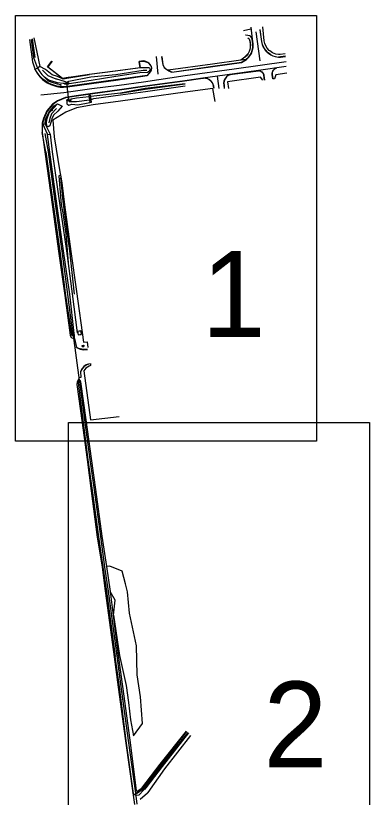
# Model space of a CAD drawing. Extents: x -866693 to -866303, y -1041966 to -1040244.
# Drawn here: x -866546.05 to -866533.7, y -1040634.99 to -1040607.7 of the extents above; entities that cross this region are included whole.
import ezdxf

# ---------------------------------------------------------------- set-up
doc = ezdxf.new("R2010")
doc.units = 0
doc.layers.add('Formát', color=7, linetype='Continuous')
doc.layers.add('Legenda', color=7, linetype='Continuous')

msp = doc.modelspace()

# ---------------------------------------------------------------- linework, layer by layer
at = {"layer": 'Legenda'}
for p, q in [((-866537.835, -1040608.174), (-866538.095, -1040608.233)), ((-866537.786, -1040608.522), (-866537.834, -1040608.107)), ((-866537.668, -1040608.26), (-866537.526, -1040609.272)), ((-866545.569, -1040608.535), (-866545.459, -1040609.311)), ((-866545.515, -1040608.528), (-866545.427, -1040609.164)), ((-866545.366, -1040609.158), (-866545.468, -1040608.506)), ((-866545.412, -1040608.473), (-866545.203, -1040609.471)), ((-866545.427, -1040609.164), (-866545.293, -1040609.528)), ((-866541.144, -1040609.123), (-866541.089, -1040609.746)), ((-866538.005, -1040609.227), (-866538.188, -1040609.253)), ((-866541.706, -1040609.521), (-866541.738, -1040609.297)), ((-866541.698, -1040609.526), (-866541.731, -1040609.302)), ((-866541.377, -1040609.52), (-866541.698, -1040609.526)), ((-866538.944, -1040610.248), (-866539.007, -1040609.813)), ((-866538.476, -1040609.752), (-866538.478, -1040609.748)), ((-866537.577, -1040609.634), (-866538.476, -1040609.752)), ((-866544.265, -1040610.05), (-866544.267, -1040610.025)), ((-866544.189, -1040610.664), (-866544.265, -1040610.048)), ((-866541.53, -1040610.27), (-866540.13, -1040610.079)), ((-866544.471, -1040610.108), (-866544.483, -1040610.179)), ((-866542.394, -1040610.407), (-866541.53, -1040610.27)), ((-866543.93, -1040610.582), (-866544.119, -1040610.621)), ((-866544.265, -1040610.667), (-866544.206, -1040610.666)), ((-866544.187, -1040610.697), (-866544.185, -1040610.664)), ((-866544.757, -1040611.028), (-866544.781, -1040610.991)), ((-866545.118, -1040611.463), (-866544.94, -1040611.848)), ((-866545.021, -1040611.488), (-866544.848, -1040611.839)), ((-866545.001, -1040612.458), (-866545.121, -1040611.78)), ((-866544.249, -1040615.9), (-866544.222, -1040616.326)), ((-866543.892, -1040618.711), (-866543.781, -1040618.695)), ((-866543.892, -1040618.711), (-866543.874, -1040618.84)), ((-866543.89, -1040618.712), (-866543.782, -1040618.696)), ((-866543.89, -1040618.712), (-866543.873, -1040618.839)), ((-866543.874, -1040618.84), (-866543.763, -1040618.824)), ((-866543.873, -1040618.839), (-866543.765, -1040618.823)), ((-866543.782, -1040618.696), (-866543.765, -1040618.823)), ((-866543.781, -1040618.695), (-866543.763, -1040618.824)), ((-866544.047, -1040618.859), (-866543.832, -1040620.423)), ((-866543.736, -1040619.209), (-866543.676, -1040619.202)), ((-866543.736, -1040619.209), (-866543.732, -1040619.253)), ((-866543.734, -1040619.211), (-866543.677, -1040619.203)), ((-866543.734, -1040619.211), (-866543.731, -1040619.251)), ((-866543.732, -1040619.253), (-866543.672, -1040619.246)), ((-866543.731, -1040619.251), (-866543.674, -1040619.244)), ((-866543.677, -1040619.203), (-866543.674, -1040619.244)), ((-866543.676, -1040619.202), (-866543.672, -1040619.246)), ((-866543.584, -1040619.898), (-866543.668, -1040619.959)), ((-866543.469, -1040619.855), (-866543.584, -1040619.898)), ((-866543.469, -1040619.855), (-866543.472, -1040619.853)), ((-866543.784, -1040620.12), (-866543.789, -1040620.117)), ((-866543.727, -1040620.025), (-866543.784, -1040620.12)), ((-866543.668, -1040619.959), (-866543.727, -1040620.025)), ((-866543.858, -1040620.4), (-866543.864, -1040620.504)), ((-866543.832, -1040620.423), (-866543.826, -1040620.485)), ((-866543.864, -1040620.504), (-866543.706, -1040621.824)), ((-866543.826, -1040620.485), (-866543.648, -1040621.813)), ((-866543.783, -1040620.484), (-866543.603, -1040621.806)), ((-866543.706, -1040621.824), (-866543.531, -1040623.204)), ((-866543.648, -1040621.813), (-866543.462, -1040623.195)), ((-866543.603, -1040621.806), (-866543.42, -1040623.162)), ((-866543.462, -1040623.195), (-866543.314, -1040624.254)), ((-866543.42, -1040623.162), (-866543.268, -1040624.239)), ((-866543.531, -1040623.204), (-866543.385, -1040624.271)), ((-866543.385, -1040624.271), (-866543.156, -1040625.894)), ((-866543.314, -1040624.254), (-866543.089, -1040625.88)), ((-866543.268, -1040624.239), (-866543.037, -1040625.869)), ((-866543.156, -1040625.894), (-866543.005, -1040626.955)), ((-866543.089, -1040625.88), (-866542.944, -1040626.947)), ((-866543.037, -1040625.869), (-866542.884, -1040626.927)), ((-866543.005, -1040626.955), (-866542.884, -1040627.79)), ((-866542.944, -1040626.947), (-866542.825, -1040627.793)), ((-866542.759, -1040626.92), (-866542.884, -1040626.927)), ((-866542.884, -1040626.927), (-866542.755, -1040627.8)), ((-866542.333, -1040627.087), (-866542.759, -1040626.92)), ((-866542.215, -1040627.528), (-866542.333, -1040627.087)), ((-866542.149, -1040627.815), (-866542.215, -1040627.528)), ((-866542.884, -1040627.79), (-866542.576, -1040630.066)), ((-866542.825, -1040627.793), (-866542.518, -1040630.045)), ((-866542.755, -1040627.8), (-866542.47, -1040630.035)), ((-866542.581, -1040628.107), (-866542.755, -1040627.8)), ((-866542.081, -1040628.559), (-866542.149, -1040627.815)), ((-866542.641, -1040628.621), (-866542.581, -1040628.107)), ((-866542.641, -1040628.621), (-866542.43, -1040630.028)), ((-866541.837, -1040629.696), (-866542.081, -1040628.559)), ((-866541.812, -1040630.703), (-866541.837, -1040629.696)), ((-866542.425, -1040631.13), (-866542.576, -1040630.066)), ((-866542.518, -1040630.045), (-866542.376, -1040631.115)), ((-866542.47, -1040630.035), (-866542.323, -1040631.111)), ((-866542.43, -1040630.028), (-866542.191, -1040631.08)), ((-866541.691, -1040631.478), (-866541.812, -1040630.703)), ((-866542.323, -1040631.111), (-866542.068, -1040632.992)), ((-866542.191, -1040631.08), (-866542.106, -1040631.678)), ((-866542.198, -1040633.008), (-866542.425, -1040631.13)), ((-866542.376, -1040631.115), (-866542.123, -1040632.999)), ((-866541.627, -1040632.407), (-866541.691, -1040631.478)), ((-866542.106, -1040631.678), (-866542.037, -1040632.276)), ((-866542.037, -1040632.276), (-866541.942, -1040632.835)), ((-866541.942, -1040632.835), (-866541.627, -1040632.407)), ((-866541.004, -1040633.829), (-866540.091, -1040632.678)), ((-866540.995, -1040633.853), (-866540.073, -1040632.691)), ((-866540.038, -1040632.717), (-866540.97, -1040633.872)), ((-866540.022, -1040632.735), (-866540.933, -1040633.904)), ((-866541.933, -1040634.854), (-866542.198, -1040633.008)), ((-866542.123, -1040632.999), (-866541.87, -1040634.838)), ((-866542.068, -1040632.992), (-866541.843, -1040634.746)), ((-866540.838, -1040633.988), (-866539.932, -1040632.831)), ((-866541.644, -1040634.667), (-866541.004, -1040633.829)), ((-866541.626, -1040634.68), (-866540.995, -1040633.853)), ((-866540.97, -1040633.872), (-866541.601, -1040634.698)), ((-866540.933, -1040633.904), (-866541.506, -1040634.655)), ((-866541.428, -1040634.819), (-866540.838, -1040633.988)), ((-866541.506, -1040634.655), (-866541.539, -1040634.695)), ((-866541.922, -1040634.902), (-866541.965, -1040634.83)), ((-866541.921, -1040634.869), (-866541.933, -1040634.854)), ((-866541.829, -1040634.919), (-866541.922, -1040634.902)), ((-866541.89, -1040634.882), (-866541.921, -1040634.869)), ((-866541.851, -1040634.875), (-866541.89, -1040634.882)), ((-866541.87, -1040634.838), (-866541.808, -1040634.814)), ((-866541.87, -1040634.838), (-866541.826, -1040635.224)), ((-866541.817, -1040634.847), (-866541.851, -1040634.875)), ((-866541.843, -1040634.746), (-866541.825, -1040634.77)), ((-866541.755, -1040634.914), (-866541.829, -1040634.919)), ((-866541.825, -1040634.77), (-866541.808, -1040634.774)), ((-866541.794, -1040634.84), (-866541.817, -1040634.847)), ((-866541.808, -1040634.774), (-866541.644, -1040634.667)), ((-866541.808, -1040634.814), (-866541.626, -1040634.68)), ((-866541.601, -1040634.698), (-866541.794, -1040634.84)), ((-866541.572, -1040634.719), (-866541.755, -1040634.914)), ((-866541.704, -1040635.051), (-866541.451, -1040634.832)), ((-866541.539, -1040634.695), (-866541.572, -1040634.719)), ((-866541.451, -1040634.832), (-866541.428, -1040634.819))]:
    msp.add_line(p, q, dxfattribs=at)
for points in [[(-866546.052, -1040607.7), (-866535.552, -1040607.7), (-866535.552, -1040622.55), (-866546.052, -1040622.55)], [(-866544.187, -1040610.076), (-866544.189, -1040610.076), (-866544.193, -1040610.046), (-866544.19, -1040610.046)], [(-866544.267, -1040610.639), (-866544.263, -1040610.665), (-866544.265, -1040610.667)], [(-866543.492, -1040610.491), (-866543.457, -1040610.727), (-866543.407, -1040610.716), (-866543.436, -1040610.479)], [(-866544.59, -1040610.777), (-866544.426, -1040610.862), (-866544.578, -1040611.031), (-866544.729, -1040611.173), (-866544.791, -1040611.303), (-866544.8, -1040611.346), (-866544.855, -1040611.541), (-866544.911, -1040611.582), (-866544.953, -1040611.568), (-866544.974, -1040611.461), (-866544.958, -1040611.323), (-866544.878, -1040611.094)], [(-866544.202, -1040621.896), (-866533.702, -1040621.896), (-866533.702, -1040636.746), (-866544.202, -1040636.746)]]:
    msp.add_lwpolyline(points, close=True, dxfattribs=at)
for points in [[(-866537.144, -1040609.069), (-866537.142, -1040609.064), (-866537.24, -1040608.996), (-866537.265, -1040608.975), (-866537.337, -1040608.894), (-866537.402, -1040608.792), (-866537.434, -1040608.705), (-866537.461, -1040608.604), (-866537.519, -1040608.187)], [(-866536.639, -1040609.035), (-866536.821, -1040609.056), (-866536.874, -1040609.058), (-866536.972, -1040609.04), (-866537.03, -1040609.025), (-866537.087, -1040608.996), (-866537.178, -1040608.932), (-866537.205, -1040608.913), (-866537.274, -1040608.833), (-866537.319, -1040608.759), (-866537.356, -1040608.673), (-866537.379, -1040608.581), (-866537.42, -1040608.096)], [(-866540.96, -1040609.132), (-866540.917, -1040609.418), (-866540.868, -1040609.505), (-866540.813, -1040609.559), (-866540.706, -1040609.627), (-866540.639, -1040609.665), (-866540.603, -1040609.676), (-866539.17, -1040609.475), (-866538.163, -1040609.333), (-866537.995, -1040609.228), (-866537.919, -1040609.16), (-866537.843, -1040609.061), (-866537.809, -1040608.996), (-866537.78, -1040608.89), (-866537.763, -1040608.81), (-866537.762, -1040608.686), (-866537.786, -1040608.522), (-866537.817, -1040608.459), (-866537.852, -1040608.418), (-866537.876, -1040608.4), (-866538.027, -1040608.376)], [(-866537.77, -1040608.81), (-866537.767, -1040608.688), (-866537.79, -1040608.523), (-866537.816, -1040608.465), (-866537.855, -1040608.42), (-866537.877, -1040608.402), (-866538.02, -1040608.38)], [(-866537.523, -1040608.196), (-866537.467, -1040608.606), (-866537.442, -1040608.709), (-866537.409, -1040608.795), (-866537.343, -1040608.899), (-866537.269, -1040608.979), (-866537.245, -1040609.001), (-866537.144, -1040609.069), (-866537.069, -1040609.102), (-866536.991, -1040609.132), (-866536.878, -1040609.151), (-866536.802, -1040609.146), (-866536.628, -1040609.125)], [(-866537.945, -1040608.477), (-866537.899, -1040608.506), (-866537.873, -1040608.586), (-866537.86, -1040608.707), (-866537.864, -1040608.818), (-866537.874, -1040608.878), (-866537.9, -1040608.955), (-866537.936, -1040609.017), (-866538.001, -1040609.097), (-866538.052, -1040609.149), (-866538.19, -1040609.25), (-866539.18, -1040609.39), (-866540.727, -1040609.607)], [(-866537.856, -1040608.706), (-866537.859, -1040608.818), (-866537.873, -1040608.878), (-866537.898, -1040608.957), (-866537.932, -1040609.019), (-866537.994, -1040609.1), (-866538.052, -1040609.152), (-866538.188, -1040609.253), (-866539.179, -1040609.393), (-866540.724, -1040609.609)], [(-866537.945, -1040608.475), (-866537.898, -1040608.505), (-866537.872, -1040608.584), (-866537.856, -1040608.706)], [(-866538.005, -1040609.227), (-866537.999, -1040609.223), (-866537.924, -1040609.155), (-866537.851, -1040609.057), (-866537.815, -1040608.995), (-866537.77, -1040608.81)], [(-866545.459, -1040609.311), (-866545.378, -1040609.557), (-866545.314, -1040609.691), (-866545.206, -1040609.835), (-866545.11, -1040609.928), (-866544.951, -1040610.044), (-866544.825, -1040610.104), (-866544.619, -1040610.173), (-866544.494, -1040610.193), (-866544.384, -1040610.194), (-866544.159, -1040610.174), (-866543.401, -1040610.07), (-866542.548, -1040609.952), (-866541.461, -1040609.793), (-866541.346, -1040609.666), (-866541.311, -1040609.599), (-866541.302, -1040609.522), (-866541.315, -1040609.47), (-866541.344, -1040609.422), (-866541.393, -1040609.366), (-866541.434, -1040609.334), (-866541.502, -1040609.3), (-866541.579, -1040609.276), (-866541.738, -1040609.297)], [(-866540.953, -1040609.131), (-866540.913, -1040609.417), (-866540.862, -1040609.503), (-866540.809, -1040609.555), (-866540.727, -1040609.607), (-866540.724, -1040609.609), (-866540.701, -1040609.622), (-866540.699, -1040609.619), (-866540.656, -1040609.641), (-866540.601, -1040609.664), (-866540.603, -1040609.669), (-866539.171, -1040609.469), (-866538.164, -1040609.323), (-866538.005, -1040609.227)], [(-866536.628, -1040609.117), (-866536.803, -1040609.141), (-866536.878, -1040609.144), (-866536.878, -1040609.151)], [(-866545.378, -1040609.557), (-866545.293, -1040609.528), (-866545.208, -1040609.662), (-866545.134, -1040609.76), (-866545.044, -1040609.849), (-866544.913, -1040609.972), (-866544.789, -1040610.023), (-866544.602, -1040610.081), (-866544.471, -1040610.108)], [(-866543.477, -1040609.762), (-866544.194, -1040609.887), (-866544.392, -1040609.915), (-866544.592, -1040609.822), (-866544.771, -1040609.768), (-866545.013, -1040609.577), (-866545.203, -1040609.471), (-866545.293, -1040609.528)], [(-866545.177, -1040610.465), (-866544.373, -1040610.386), (-866543.389, -1040610.249), (-866542.434, -1040610.132), (-866541.584, -1040610.005), (-866540.138, -1040609.794), (-866538.42, -1040609.551), (-866536.612, -1040609.303)], [(-866536.604, -1040609.481), (-866537.578, -1040609.615), (-866538.495, -1040609.742), (-866539.516, -1040609.884), (-866540.146, -1040609.972), (-866541.546, -1040610.166), (-866542.425, -1040610.288), (-866543.364, -1040610.419), (-866543.936, -1040610.495), (-866544.314, -1040610.554), (-866544.596, -1040610.669), (-866544.761, -1040610.788), (-866544.962, -1040611.022), (-866545.084, -1040611.291), (-866545.13, -1040611.458), (-866545.121, -1040611.78), (-866545.032, -1040612.453), (-866544.765, -1040614.369), (-866544.556, -1040615.923), (-866544.339, -1040617.471), (-866544.145, -1040618.855), (-866544.109, -1040618.933), (-866544.06, -1040618.96), (-866543.995, -1040618.974), (-866543.928, -1040619.282), (-866543.848, -1040619.324), (-866543.802, -1040619.339), (-866543.688, -1040619.36), (-866543.54, -1040619.35)], [(-866541.698, -1040609.526), (-866542.571, -1040609.642), (-866543.472, -1040609.757), (-866544.195, -1040609.859), (-866544.414, -1040609.89), (-866544.94, -1040609.485), (-866544.787, -1040609.291)], [(-866544.775, -1040609.289), (-866544.929, -1040609.488), (-866544.412, -1040609.881), (-866544.216, -1040609.853), (-866543.625, -1040609.772)], [(-866541.377, -1040609.52), (-866541.35, -1040609.568), (-866541.385, -1040609.651), (-866541.446, -1040609.683), (-866541.714, -1040609.7), (-866542.553, -1040609.827), (-866543.418, -1040609.962), (-866544.187, -1040610.076)], [(-866541.706, -1040609.521), (-866542.578, -1040609.637), (-866543.48, -1040609.751), (-866543.625, -1040609.772)], [(-866541.731, -1040609.302), (-866541.574, -1040609.286), (-866541.505, -1040609.308), (-866541.437, -1040609.341), (-866541.397, -1040609.372), (-866541.35, -1040609.426), (-866541.322, -1040609.472), (-866541.31, -1040609.521), (-866541.319, -1040609.597), (-866541.354, -1040609.665), (-866541.465, -1040609.79), (-866542.56, -1040609.946)], [(-866536.952, -1040609.544), (-866536.97, -1040609.547), (-866536.995, -1040609.555), (-866537.015, -1040609.567), (-866537.037, -1040609.582), (-866537.055, -1040609.6), (-866537.074, -1040609.62), (-866537.084, -1040609.64), (-866537.101, -1040609.679), (-866537.104, -1040609.703), (-866537.103, -1040609.761), (-866537.082, -1040609.909)], [(-866536.952, -1040609.544), (-866536.951, -1040609.549), (-866536.992, -1040609.562), (-866537.011, -1040609.574), (-866537.033, -1040609.589), (-866537.068, -1040609.624), (-866537.093, -1040609.681), (-866537.097, -1040609.703), (-866537.096, -1040609.76), (-866537.074, -1040609.905)], [(-866542.56, -1040609.946), (-866543.405, -1040610.056), (-866544.16, -1040610.163), (-866544.384, -1040610.18), (-866544.492, -1040610.178), (-866544.615, -1040610.158), (-866544.819, -1040610.092), (-866544.942, -1040610.031), (-866545.102, -1040609.914), (-866545.197, -1040609.824), (-866545.302, -1040609.681), (-866545.378, -1040609.557)], [(-866545.109, -1040609.608), (-866544.924, -1040609.785), (-866544.648, -1040609.907), (-866544.622, -1040609.906), (-866544.362, -1040609.986), (-866544.267, -1040610.025), (-866544.193, -1040609.988), (-866543.423, -1040609.838), (-866542.559, -1040609.753), (-866541.595, -1040609.604), (-866541.475, -1040609.604)], [(-866538.495, -1040609.742), (-866538.568, -1040609.758), (-866538.632, -1040609.787), (-866538.696, -1040609.837), (-866538.744, -1040609.901), (-866538.779, -1040609.985), (-866538.792, -1040610.061), (-866538.789, -1040610.126), (-866538.776, -1040610.24)], [(-866538.478, -1040609.748), (-866538.495, -1040609.749), (-866538.565, -1040609.764), (-866538.63, -1040609.793), (-866538.69, -1040609.839), (-866538.74, -1040609.907), (-866538.77, -1040609.986), (-866538.781, -1040610.062), (-866538.777, -1040610.128), (-866538.768, -1040610.239)], [(-866537.355, -1040609.947), (-866537.378, -1040609.787), (-866537.38, -1040609.777), (-866537.39, -1040609.741), (-866537.397, -1040609.724), (-866537.408, -1040609.706), (-866537.435, -1040609.675), (-866537.464, -1040609.656), (-866537.488, -1040609.645), (-866537.524, -1040609.634), (-866537.578, -1040609.615)], [(-866537.577, -1040609.634), (-866537.577, -1040609.634), (-866537.577, -1040609.627), (-866537.578, -1040609.615)], [(-866537.359, -1040609.947), (-866537.386, -1040609.777), (-866537.402, -1040609.731), (-866537.442, -1040609.681), (-866537.49, -1040609.653), (-866537.527, -1040609.641), (-866537.577, -1040609.627)], [(-866536.582, -1040609.706), (-866536.967, -1040609.763), (-866537.019, -1040609.902), (-866537.068, -1040609.908)], [(-866539.134, -1040610.235), (-866539.145, -1040610.16), (-866539.159, -1040610.104), (-866539.184, -1040610.048), (-866539.229, -1040609.992), (-866539.279, -1040609.95), (-866539.324, -1040609.923), (-866539.366, -1040609.905), (-866539.41, -1040609.892), (-866539.451, -1040609.885), (-866539.496, -1040609.889), (-866539.515, -1040609.89), (-866539.517, -1040609.896), (-866540.158, -1040609.986), (-866541.544, -1040610.179), (-866542.423, -1040610.303), (-866543.357, -1040610.432), (-866543.931, -1040610.509), (-866544.31, -1040610.567), (-866544.59, -1040610.683), (-866544.63, -1040610.707), (-866544.752, -1040610.801), (-866544.949, -1040611.03), (-866545.066, -1040611.301), (-866545.118, -1040611.463), (-866545.13, -1040611.458)], [(-866544.341, -1040610.063), (-866544.393, -1040610.073), (-866544.589, -1040610.046), (-866544.773, -1040609.985), (-866544.902, -1040609.952), (-866545.044, -1040609.849)], [(-866544.193, -1040610.046), (-866544.341, -1040610.063), (-866544.336, -1040610.091), (-866544.189, -1040610.076)], [(-866544.341, -1040610.063), (-866544.283, -1040610.052), (-866544.265, -1040610.05), (-866544.251, -1040610.049), (-866544.19, -1040610.046)], [(-866540.13, -1040610.079), (-866541.533, -1040610.238), (-866542.394, -1040610.407), (-866543.325, -1040610.516), (-866543.43, -1040610.525)], [(-866539.126, -1040610.234), (-866539.136, -1040610.158), (-866539.15, -1040610.101), (-866539.181, -1040610.045), (-866539.223, -1040609.988), (-866539.275, -1040609.945), (-866539.32, -1040609.919), (-866539.362, -1040609.899), (-866539.408, -1040609.885), (-866539.451, -1040609.879), (-866539.516, -1040609.884)], [(-866537.421, -1040609.956), (-866537.507, -1040609.842), (-866538.652, -1040610.005), (-866538.625, -1040610.239)], [(-866539.088, -1040610.697), (-866539.166, -1040610.245), (-866540.133, -1040610.374), (-866541.476, -1040610.563), (-866542.391, -1040610.689), (-866543.343, -1040610.817), (-866543.926, -1040610.913), (-866544.299, -1040611.065), (-866544.752, -1040611.351), (-866544.711, -1040611.926), (-866544.511, -1040613.149), (-866544.481, -1040613.272), (-866544.442, -1040613.541), (-866544.346, -1040614.299), (-866544.121, -1040615.938), (-866543.926, -1040617.326), (-866543.679, -1040619.097), (-866543.552, -1040619.081), (-866543.529, -1040619.284)], [(-866543.317, -1040610.589), (-866542.395, -1040610.46), (-866541.515, -1040610.344), (-866540.137, -1040610.146)], [(-866544.26, -1040610.665), (-866544.116, -1040610.648), (-866544.119, -1040610.621), (-866544.267, -1040610.639)], [(-866544.206, -1040610.666), (-866544.185, -1040610.664), (-866544.169, -1040610.66), (-866544.147, -1040610.66), (-866544.114, -1040610.646)], [(-866544.187, -1040610.697), (-866543.923, -1040610.692), (-866543.476, -1040610.639)], [(-866544.116, -1040610.648), (-866544.114, -1040610.646), (-866544.119, -1040610.621)], [(-866543.486, -1040610.534), (-866543.93, -1040610.582)], [(-866543.492, -1040610.491), (-866543.476, -1040610.639), (-866543.457, -1040610.727)], [(-866543.407, -1040610.716), (-866543.413, -1040610.631), (-866543.436, -1040610.479)], [(-866543.413, -1040610.631), (-866543.317, -1040610.589)], [(-866545.118, -1040611.463), (-866545.021, -1040611.488), (-866545.005, -1040611.314), (-866544.897, -1040611.085), (-866544.706, -1040610.853), (-866544.59, -1040610.777)], [(-866544.265, -1040610.667), (-866544.261, -1040610.778), (-866544.191, -1040610.82), (-866544.091, -1040610.79), (-866543.882, -1040610.81), (-866543.457, -1040610.727)], [(-866544.629, -1040610.94), (-866544.794, -1040611.126), (-866544.859, -1040611.285), (-866544.895, -1040611.438)], [(-866545.031, -1040611.816), (-866544.917, -1040612.456), (-866544.655, -1040614.354), (-866544.442, -1040615.919), (-866544.238, -1040617.433), (-866544.062, -1040618.788), (-866544.047, -1040618.859)], [(-866543.995, -1040618.974), (-866543.995, -1040618.843), (-866544.006, -1040618.791), (-866544.165, -1040617.421), (-866544.381, -1040615.915), (-866544.6, -1040614.347), (-866544.859, -1040612.462), (-866544.94, -1040611.848), (-866544.848, -1040611.839), (-866544.78, -1040612.459), (-866544.505, -1040614.331), (-866544.276, -1040615.904), (-866544.083, -1040617.411), (-866543.906, -1040618.773)], [(-866545.001, -1040612.458), (-866544.735, -1040614.37), (-866544.514, -1040615.921), (-866544.316, -1040617.465), (-866544.104, -1040618.844), (-866544.067, -1040618.867), (-866544.041, -1040618.863), (-866544.03, -1040618.85), (-866544.006, -1040618.791)], [(-866544.481, -1040613.272), (-866544.54, -1040613.292), (-866544.459, -1040614.309), (-866544.409, -1040614.588), (-866544.3, -1040615.314), (-866544.249, -1040615.9)], [(-866544.482, -1040613.354), (-866544.407, -1040614.185), (-866544.169, -1040615.904), (-866544.013, -1040617.426)], [(-866543.928, -1040619.282), (-866543.924, -1040619.277), (-866543.845, -1040619.316)], [(-866543.558, -1040619.346), (-866543.686, -1040619.354), (-866543.802, -1040619.331), (-866543.845, -1040619.316)], [(-866543.472, -1040619.853), (-866543.588, -1040619.894), (-866543.67, -1040619.952), (-866543.73, -1040620.02), (-866543.789, -1040620.117), (-866543.773, -1040620.33), (-866543.839, -1040620.342), (-866543.909, -1040620.48), (-866543.91, -1040620.574), (-866543.743, -1040621.827), (-866543.56, -1040623.193), (-866543.416, -1040624.281), (-866543.201, -1040625.902), (-866543.036, -1040626.956), (-866542.921, -1040627.782), (-866542.617, -1040630.077), (-866542.468, -1040631.135), (-866542.222, -1040633.007), (-866541.965, -1040634.83), (-866541.906, -1040635.237)], [(-866543.444, -1040619.838), (-866543.435, -1040619.914), (-866543.49, -1040619.932), (-866543.597, -1040619.999), (-866543.673, -1040620.102), (-866543.444, -1040621.806), (-866542.44, -1040621.695)], [(-866543.858, -1040620.4), (-866543.815, -1040620.407), (-866543.783, -1040620.484)]]:
    msp.add_lwpolyline(points, dxfattribs=at)

# ---------------------------------------------------------------- texts
at = {"layer": 'Formát'}
for s, p in [('1', (-866539.56, -1040618.917)), ('2', (-866537.401, -1040633.942))]:
    msp.add_text(s, height=3, dxfattribs=at).set_placement(p)

doc.saveas('drawing.dxf')
